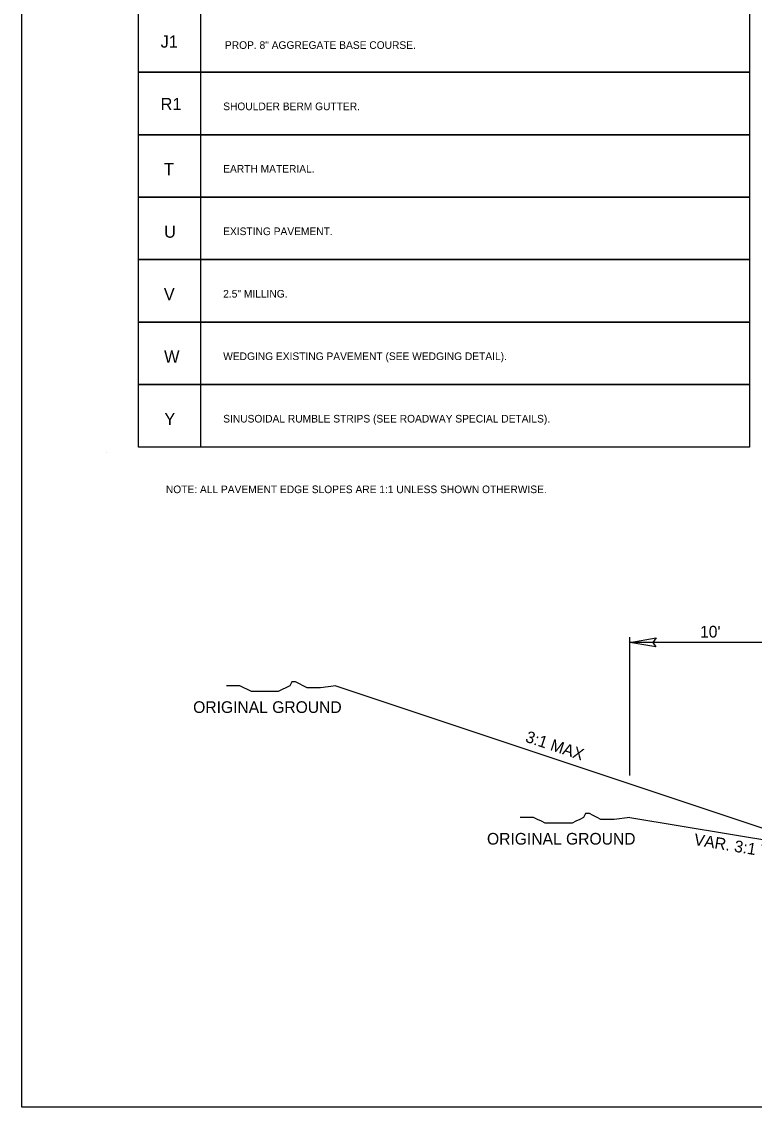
# Model space of a CAD drawing. Extents: x 1548135 to 1549339, y 868664 to 869085.
# Drawn here: x 1548135.7 to 1548182.7, y 868939.3 to 869009 of the extents above; entities that cross this region are included whole.
import ezdxf

# ---------------------------------------------------------------- set-up
doc = ezdxf.new("R2010")
doc.units = 0
for name, color, linetype in [('Default', 7, 'Continuous'), ('P_RDY_TC_Pvmt_Asphalt_Base_Course', 7, 'Continuous'), ('Sheet_Data_Field_CELL', 7, 'Continuous'), ('Typical Grade Point Symbol CELL', 7, 'Continuous'), ('Typical Hinge Slope Interstate CELL', 7, 'Continuous'), ('Typical Shoulder Slope CELL', 7, 'Continuous')]:
    doc.layers.add(name, color=color, linetype=linetype)

msp = doc.modelspace()

# ---------------------------------------------------------------- linework, layer by layer
at = {"layer": 'Default'}
msp.add_lwpolyline([(1548135.738, 869049.324), (1548305.738, 869049.324), (1548305.738, 868939.324), (1548135.738, 868939.324)], close=True, dxfattribs=at)
at = {"layer": 'P_RDY_TC_Pvmt_Asphalt_Base_Course'}
msp.add_lwpolyline([(1548176.427, 868968.866), (1548174.739, 868969.157), (1548176.436, 868969.457), (1548176.221, 868969.157)], close=True, dxfattribs=at)
at = {"layer": 'Sheet_Data_Field_CELL'}
for p, q in [((1548155.89, 868966.373), (1548184.738, 868956.757)), ((1548174.739, 868957.923), (1548190.738, 868955.257))]:
    msp.add_line(p, q, dxfattribs=at)
for points in [[(1548155.89, 868966.373), (1548154.904, 868966.25), (1548154.658, 868966.25), (1548154.288, 868966.25), (1548154.042, 868966.25), (1548153.795, 868966.373), (1548153.549, 868966.497), (1548153.303, 868966.62), (1548153.056, 868966.62), (1548152.933, 868966.373), (1548152.686, 868966.25), (1548152.44, 868966.127), (1548152.193, 868966.004), (1548151.947, 868966.004), (1548151.701, 868966.004), (1548151.454, 868966.004), (1548151.208, 868966.004), (1548150.962, 868966.004), (1548150.715, 868966.004), (1548150.469, 868966.004), (1548150.223, 868966.127), (1548149.976, 868966.25), (1548149.73, 868966.373), (1548149.36, 868966.373), (1548149.113, 868966.373), (1548148.867, 868966.373)], [(1548174.739, 868957.923), (1548173.754, 868957.801), (1548173.508, 868957.801), (1548173.138, 868957.801), (1548172.891, 868957.801), (1548172.645, 868957.923), (1548172.398, 868958.047), (1548172.152, 868958.171), (1548171.906, 868958.171), (1548171.782, 868957.923), (1548171.536, 868957.801), (1548171.289, 868957.677), (1548171.043, 868957.554), (1548170.797, 868957.554), (1548170.55, 868957.554), (1548170.304, 868957.554), (1548170.057, 868957.554), (1548169.811, 868957.554), (1548169.565, 868957.554), (1548169.318, 868957.554), (1548169.072, 868957.677), (1548168.826, 868957.801), (1548168.579, 868957.923), (1548168.209, 868957.923), (1548167.963, 868957.923), (1548167.716, 868957.923)]]:
    msp.add_lwpolyline(points, dxfattribs=at)
at = {"layer": 'Typical Grade Point Symbol CELL'}
for p, q in [((1548174.741, 868960.621), (1548174.739, 868969.502)), ((1548220.738, 868969.157), (1548174.74, 868969.157))]:
    msp.add_line(p, q, dxfattribs=at)
at = {"layer": 'Typical Hinge Slope Interstate CELL'}
msp.add_line((1548141.181, 868981.359), (1548141.181, 868981.359), dxfattribs=at)
for points in [[(1548147.232, 869005.754), (1548143.223, 869005.754), (1548143.223, 869009.763), (1548182.423, 869009.763), (1548182.423, 869005.754), (1548147.232, 869005.754), (1548147.232, 869009.763)], [(1548147.232, 869001.745), (1548143.223, 869001.745), (1548143.223, 869005.754), (1548182.423, 869005.754), (1548182.423, 869001.745), (1548147.232, 869001.745), (1548147.232, 869005.754)], [(1548147.232, 868997.736), (1548143.223, 868997.736), (1548143.223, 869001.745), (1548182.423, 869001.745), (1548182.423, 868997.736), (1548147.232, 868997.736), (1548147.232, 869001.745)], [(1548147.232, 868993.727), (1548143.223, 868993.727), (1548143.223, 868997.736), (1548182.423, 868997.736), (1548182.423, 868993.727), (1548147.232, 868993.727), (1548147.232, 868997.736)], [(1548147.232, 868989.717), (1548143.223, 868989.717), (1548143.223, 868993.727), (1548182.423, 868993.727), (1548182.423, 868989.717), (1548147.232, 868989.717), (1548147.232, 868993.727)], [(1548147.232, 868985.708), (1548143.223, 868985.708), (1548143.223, 868989.717), (1548182.423, 868989.717), (1548182.423, 868985.708), (1548147.232, 868985.708), (1548147.232, 868989.717)], [(1548147.232, 868981.699), (1548143.223, 868981.699), (1548143.223, 868985.708), (1548182.423, 868985.708), (1548182.423, 868981.699), (1548147.232, 868981.699), (1548147.232, 868985.708)]]:
    msp.add_lwpolyline(points, dxfattribs=at)

# ---------------------------------------------------------------- texts
at = {"layer": 'Sheet_Data_Field_CELL'}
for p in [(1548146.736, 868964.632), (1548165.585, 868956.182)]:
    msp.add_text('ORIGINAL GROUND', height=0.75, dxfattribs=at).set_placement(p)
for s, rotation, p in [('3:1 MAX', 341.56503, (1548168.001, 868962.794)), ('VAR. 3:1 TO 6:1', 350.53767, (1548178.824, 868956.165))]:
    msp.add_text(s, height=0.75, rotation=rotation, dxfattribs=at).set_placement(p)
at = {"layer": 'Typical Hinge Slope Interstate CELL'}
for s, height, p in [('J1', 0.784, (1548144.647, 869007.329)), ('PROP. 8" AGGREGATE BASE COURSE.', 0.49, (1548148.774, 869007.251)), ('R1', 0.784, (1548144.647, 869003.32)), ('SHOULDER BERM GUTTER.', 0.49, (1548148.662, 869003.317)), ('T', 0.784, (1548144.861, 868999.141)), ('EARTH MATERIAL.', 0.49, (1548148.662, 868999.308)), ('U', 0.784, (1548144.871, 868995.132)), ('EXISTING PAVEMENT.', 0.49, (1548148.662, 868995.299)), ('V', 0.784, (1548144.853, 868991.123)), ('2.5" MILLING.', 0.49, (1548148.662, 868991.29)), ('W', 0.784, (1548144.871, 868987.114)), ('WEDGING EXISTING PAVEMENT (SEE WEDGING DETAIL).', 0.49, (1548148.662, 868987.281)), ('Y', 0.784, (1548144.888, 868983.105)), ('SINUSOIDAL RUMBLE STRIPS (SEE ROADWAY SPECIAL DETAILS).', 0.49, (1548148.662, 868983.272)), ('NOTE: ALL PAVEMENT EDGE SLOPES ARE 1:1 UNLESS SHOWN OTHERWISE. ', 0.49, (1548144.987, 868978.739))]:
    msp.add_text(s, height=height, dxfattribs=at).set_placement(p)
at = {"layer": 'Typical Shoulder Slope CELL'}
msp.add_text("10'", height=0.75, dxfattribs=at).set_placement((1548179.255, 868969.473))

doc.saveas('drawing.dxf')
